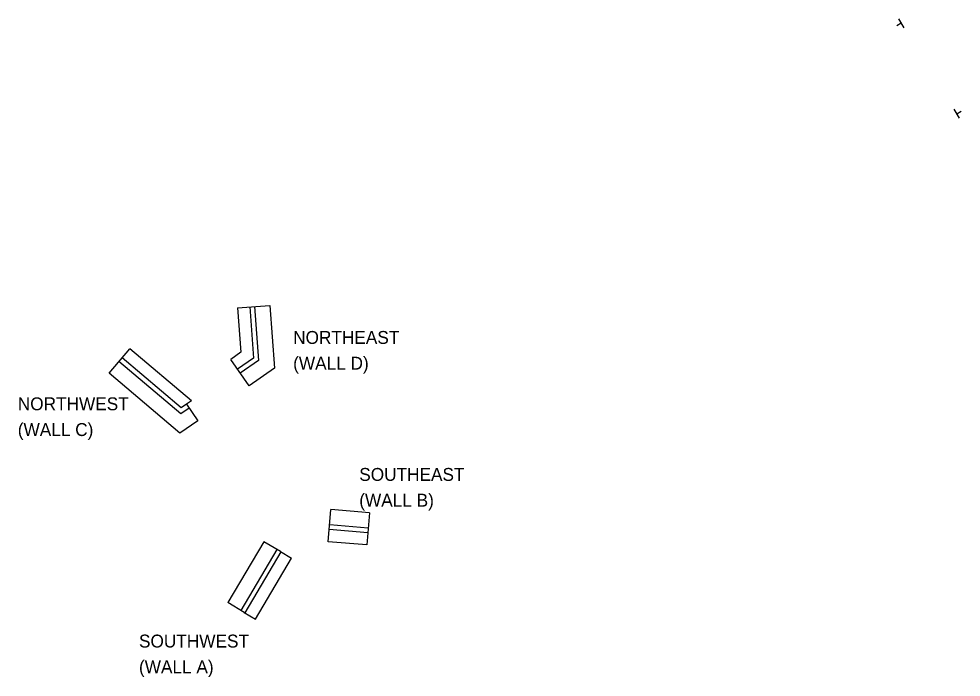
# Model space of a CAD drawing. Extents: x 2352375 to 2352668, y 766891 to 767096.
import ezdxf

# ---------------------------------------------------------------- set-up
doc = ezdxf.new("R2010")
doc.units = 0
for name, color, linetype in [('BR_P_Sub_Foot_Object', 7, 'Continuous'), ('DR_P_Headwall', 7, 'Continuous'), ('DR_X_Headwall', 7, 'Continuous'), ('GE_P_Alignment_100_Stations', 7, 'Continuous')]:
    doc.layers.add(name, color=color, linetype=linetype)

msp = doc.modelspace()

# ---------------------------------------------------------------- linework, layer by layer
at = {"layer": 'BR_P_Sub_Foot_Object'}
for p, q in [((2352443.31, 767005.83), (2352453.29, 767006.56)), ((2352443.31, 767005.83), (2352444.32, 766992.01)), ((2352453.29, 767006.56), (2352454.71, 766987.05)), ((2352403.38, 766985.47), (2352409.84, 766993.1)), ((2352428.94, 766976.93), (2352409.84, 766993.1)), ((2352444.32, 766992.01), (2352441.15, 766989.81)), ((2352446.85, 766981.59), (2352441.15, 766989.81)), ((2352425.36, 766966.86), (2352403.38, 766985.47)), ((2352454.71, 766987.05), (2352446.85, 766981.59)), ((2352428.94, 766976.93), (2352427.38, 766975.87)), ((2352427.38, 766975.87), (2352430.94, 766970.74)), ((2352430.94, 766970.74), (2352425.36, 766966.86)), ((2352471.46, 766933.18), (2352472.31, 766943.15)), ((2352484.26, 766942.14), (2352472.31, 766943.15)), ((2352484.26, 766942.14), (2352483.42, 766932.17)), ((2352451.43, 766933.18), (2352440.22, 766914.25)), ((2352456.59, 766930.12), (2352451.43, 766933.18)), ((2352483.42, 766932.17), (2352471.46, 766933.18)), ((2352456.59, 766930.12), (2352460.03, 766928.09)), ((2352448.82, 766909.16), (2352460.03, 766928.09)), ((2352445.38, 766911.19), (2352440.22, 766914.25)), ((2352445.38, 766911.19), (2352448.82, 766909.16))]:
    msp.add_line(p, q, dxfattribs=at)
at = {"layer": 'DR_P_Headwall'}
for p, q in [((2352447.05, 767006.11), (2352448.22, 766990.15)), ((2352448.55, 767006.21), (2352449.78, 766989.4)), ((2352425.65, 766972.85), (2352406.45, 766989.09)), ((2352425.74, 766974.73), (2352407.42, 766990.24)), ((2352448.22, 766990.15), (2352443.29, 766986.73)), ((2352449.78, 766989.4), (2352444.14, 766985.5)), ((2352428.23, 766974.64), (2352425.65, 766972.85)), ((2352427.38, 766975.87), (2352425.74, 766974.73)), ((2352483.86, 766937.41), (2352471.91, 766938.41)), ((2352483.74, 766935.91), (2352471.78, 766936.92)), ((2352455.52, 766930.76), (2352444.31, 766911.83)), ((2352445.6, 766911.07), (2352456.81, 766930))]:
    msp.add_line(p, q, dxfattribs=at)
at = {"layer": 'DR_X_Headwall'}
for p, q in [((2352649.47, 767094.17), (2352648.1, 767093.35)), ((2352648.65, 767095.54), (2352650.29, 767092.8)), ((2352667.52, 767064.71), (2352665.88, 767067.45)), ((2352666.7, 767066.08), (2352668.07, 767066.9))]:
    msp.add_line(p, q, dxfattribs=at)

# ---------------------------------------------------------------- texts
at = {"layer": 'GE_P_Alignment_100_Stations'}
for s, p in [('NORTHEAST', (2352460.55, 766994.61)), ('(WALL D)', (2352460.55, 766986.61)), ('NORTHWEST', (2352375.01, 766974)), ('(WALL C)', (2352375.01, 766966)), ('SOUTHEAST', (2352481.09, 766952.07)), ('(WALL B)', (2352481.09, 766944.07)), ('SOUTHWEST', (2352412.66, 766900.32)), ('(WALL A)', (2352412.66, 766892.32))]:
    msp.add_text(s, height=4, dxfattribs=at).set_placement(p)

doc.saveas('drawing.dxf')
